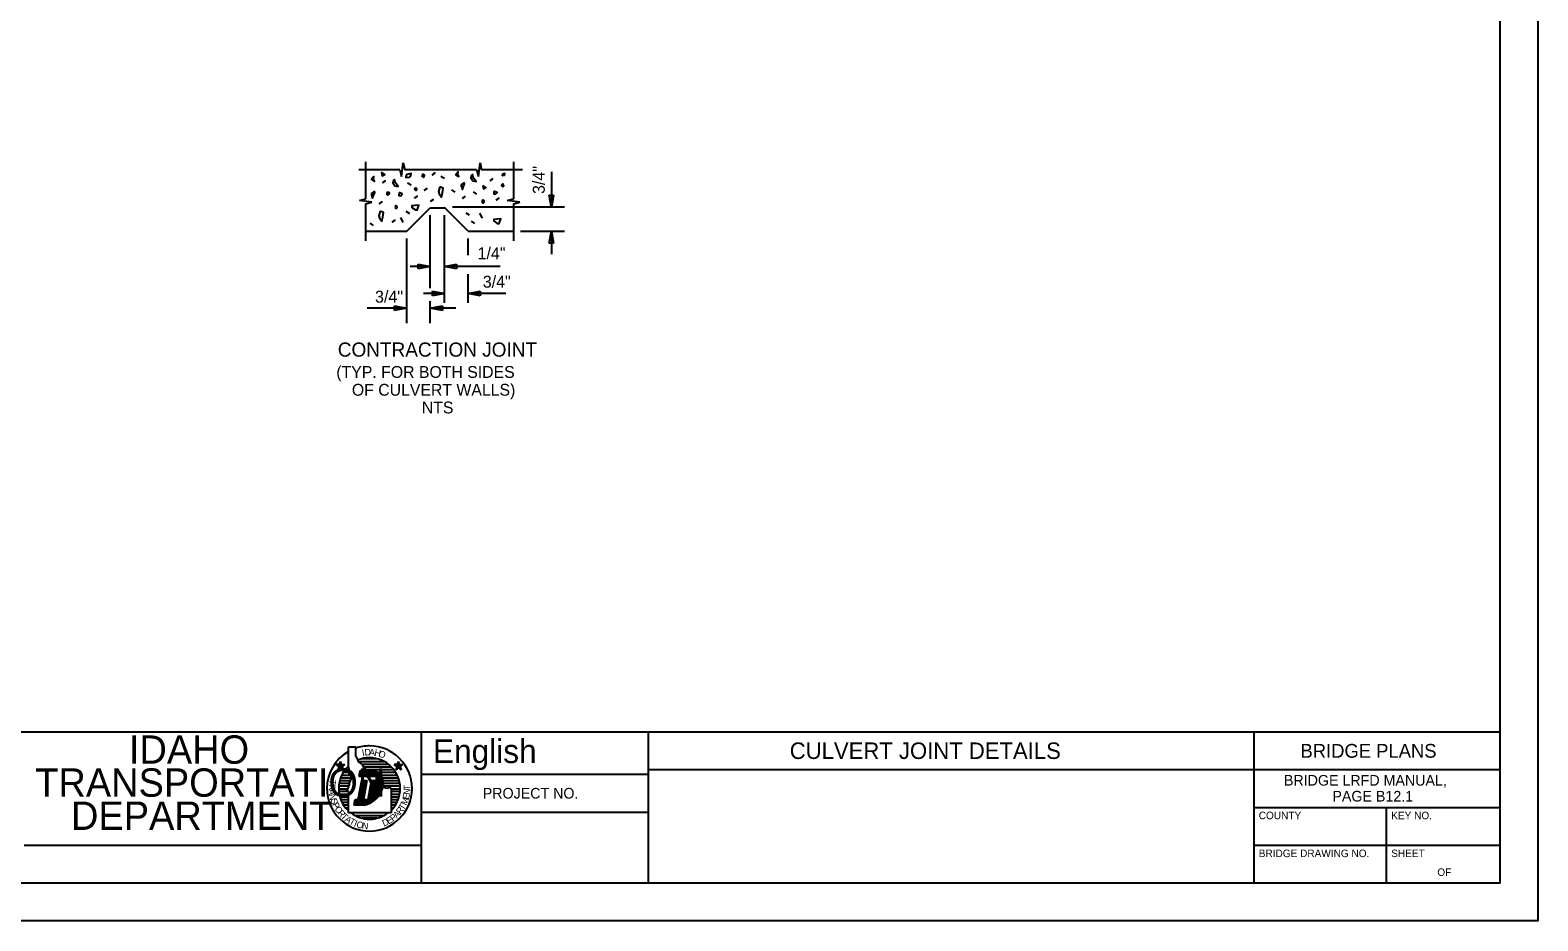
# Model space of a CAD drawing. Extents: x 0 to 22.7, y 0 to 15.7.
# Drawn here: x 9.39 to 22.67, y 0 to 7.85 of the extents above; entities that cross this region are included whole.
import ezdxf

# ---------------------------------------------------------------- set-up
doc = ezdxf.new("R2010")
doc.units = 0
for name, color, linetype in [('BORDER_ANNO_Cutsheet', 7, 'Continuous'), ('BRDG_ANNO_Anno-Sheet', 7, 'Continuous'), ('BRDG_ANNO_General-Notes', 7, 'Continuous'), ('BRDG_BASE_Obj-Line', 7, 'Continuous'), ('BRDG_BASE_Pattern', 7, 'Continuous')]:
    doc.layers.add(name, color=color, linetype=linetype)

msp = doc.modelspace()

# ---------------------------------------------------------------- linework, layer by layer
at = {"layer": 'BORDER_ANNO_Cutsheet'}
msp.add_lwpolyline([(0, 14.667), (22.667, 14.667), (22.667, 0), (0, 0)], close=True, dxfattribs=at)
at = {"layer": 'BRDG_ANNO_Anno-Sheet'}
for p, q in [((1, 1.667), (12.833, 1.667)), ((12.833, 0.333), (12.833, 1.667)), ((12.833, 1.667), (22.333, 1.667)), ((14.833, 0.333), (14.833, 1.667)), ((20.167, 0.333), (20.167, 1.667)), ((12.19, 1.362), (12.19, 1.535)), ((12.19, 1.535), (12.255, 1.535)), ((12.255, 1.449), (12.255, 1.535)), ((12.134, 1.36), (12.082, 1.377)), ((12.11, 1.377), (12.082, 1.377)), ((12.105, 1.36), (12.082, 1.377)), ((12.129, 1.377), (12.096, 1.332)), ((12.105, 1.36), (12.096, 1.332)), ((12.12, 1.349), (12.096, 1.332)), ((12.105, 1.36), (12.158, 1.377)), ((12.11, 1.377), (12.12, 1.405)), ((12.11, 1.377), (12.143, 1.332)), ((12.12, 1.349), (12.12, 1.405)), ((12.129, 1.377), (12.12, 1.405)), ((12.12, 1.349), (12.143, 1.332)), ((12.129, 1.377), (12.158, 1.377)), ((12.134, 1.36), (12.158, 1.377)), ((12.134, 1.36), (12.143, 1.332)), ((12.161, 1.334), (12.196, 1.334)), ((12.183, 1.357), (12.191, 1.357)), ((12.196, 1.337), (12.19, 1.362)), ((12.196, 1.317), (12.196, 1.337)), ((12.255, 1.449), (12.273, 1.417)), ((12.273, 1.417), (12.276, 1.403)), ((12.276, 1.403), (12.311, 1.379)), ((12.278, 1.405), (12.5, 1.405)), ((12.31, 1.43), (12.439, 1.43)), ((12.31, 1.382), (12.538, 1.382)), ((12.311, 1.379), (12.322, 1.351)), ((12.319, 1.357), (12.567, 1.357)), ((12.322, 1.351), (12.356, 1.324)), ((12.344, 1.334), (12.588, 1.334)), ((12.645, 1.36), (12.592, 1.377)), ((12.616, 1.36), (12.592, 1.377)), ((12.621, 1.377), (12.592, 1.377)), ((12.64, 1.377), (12.607, 1.332)), ((12.616, 1.36), (12.607, 1.332)), ((12.63, 1.349), (12.607, 1.332)), ((12.616, 1.36), (12.668, 1.377)), ((12.621, 1.377), (12.63, 1.405)), ((12.621, 1.377), (12.654, 1.332)), ((12.63, 1.349), (12.63, 1.405)), ((12.64, 1.377), (12.63, 1.405)), ((12.63, 1.349), (12.654, 1.332)), ((12.64, 1.377), (12.668, 1.377)), ((12.645, 1.36), (12.668, 1.377)), ((12.645, 1.36), (12.654, 1.332)), ((14.833, 1.333), (20.167, 1.333)), ((20.167, 1.333), (22.333, 1.333)), ((12.108, 1.214), (12.199, 1.214)), ((12.114, 1.238), (12.207, 1.238)), ((12.121, 1.262), (12.213, 1.262)), ((12.131, 1.285), (12.199, 1.285)), ((12.145, 1.31), (12.195, 1.31)), ((12.19, 1.181), (12.2, 1.202)), ((12.196, 1.299), (12.196, 1.317)), ((12.2, 1.285), (12.196, 1.299)), ((12.214, 1.278), (12.2, 1.285)), ((12.2, 1.219), (12.207, 1.233)), ((12.2, 1.202), (12.2, 1.219)), ((12.207, 1.233), (12.214, 1.25)), ((12.214, 1.261), (12.214, 1.278)), ((12.214, 1.25), (12.214, 1.261)), ((12.276, 1.07), (12.307, 1.237)), ((12.277, 1.021), (12.318, 1.237)), ((12.283, 1.271), (12.294, 1.324)), ((12.441, 1.271), (12.283, 1.271)), ((12.288, 1.021), (12.329, 1.237)), ((12.293, 1.271), (12.303, 1.324)), ((12.294, 1.324), (12.408, 1.324)), ((12.299, 1.021), (12.339, 1.237)), ((12.303, 1.271), (12.313, 1.324)), ((12.307, 1.237), (12.353, 1.237)), ((12.31, 1.021), (12.35, 1.237)), ((12.314, 1.271), (12.324, 1.324)), ((12.353, 1.237), (12.322, 1.07)), ((12.325, 1.271), (12.335, 1.324)), ((12.335, 1.271), (12.345, 1.324)), ((12.346, 1.271), (12.355, 1.324)), ((12.356, 1.271), (12.366, 1.324)), ((12.362, 1.07), (12.394, 1.237)), ((12.365, 1.032), (12.403, 1.237)), ((12.367, 1.271), (12.377, 1.324)), ((12.376, 1.037), (12.413, 1.237)), ((12.377, 1.271), (12.387, 1.324)), ((12.387, 1.042), (12.424, 1.237)), ((12.388, 1.271), (12.398, 1.324)), ((12.394, 1.237), (12.435, 1.237)), ((12.399, 1.271), (12.409, 1.324)), ((12.4, 1.05), (12.448, 1.308)), ((12.409, 1.271), (12.419, 1.321)), ((12.412, 1.057), (12.457, 1.301)), ((12.42, 1.271), (12.429, 1.318)), ((12.424, 1.067), (12.466, 1.292)), ((12.43, 1.271), (12.438, 1.313)), ((12.435, 1.237), (12.441, 1.271)), ((12.437, 1.079), (12.475, 1.283)), ((12.446, 1.31), (12.605, 1.31)), ((12.45, 1.093), (12.483, 1.271)), ((12.465, 1.113), (12.491, 1.255)), ((12.473, 1.285), (12.618, 1.285)), ((12.481, 1.145), (12.497, 1.23)), ((12.488, 1.262), (12.629, 1.262)), ((12.496, 1.238), (12.636, 1.238)), ((12.498, 1.214), (12.642, 1.214)), ((12.833, 1.292), (14.833, 1.292)), ((12.104, 1.165), (12.185, 1.165)), ((12.105, 1.19), (12.194, 1.19)), ((12.105, 1.142), (12.188, 1.142)), ((12.109, 1.117), (12.199, 1.117)), ((12.114, 1.094), (12.189, 1.094)), ((12.122, 1.07), (12.188, 1.07)), ((12.179, 1.15), (12.186, 1.167)), ((12.19, 1.14), (12.179, 1.15)), ((12.186, 1.167), (12.19, 1.181)), ((12.196, 1.129), (12.19, 1.14)), ((12.19, 1.101), (12.2, 1.112)), ((12.19, 0.952), (12.19, 1.101)), ((12.2, 1.122), (12.196, 1.129)), ((12.2, 1.112), (12.2, 1.122)), ((12.24, 1.021), (12.249, 1.07)), ((12.246, 1.021), (12.255, 1.07)), ((12.249, 1.07), (12.276, 1.07)), ((12.257, 1.021), (12.266, 1.07)), ((12.267, 1.021), (12.276, 1.07)), ((12.32, 1.021), (12.329, 1.07)), ((12.322, 1.07), (12.362, 1.07)), ((12.331, 1.022), (12.34, 1.07)), ((12.342, 1.025), (12.35, 1.07)), ((12.353, 1.028), (12.361, 1.07)), ((12.494, 1.185), (12.499, 1.177)), ((12.495, 1.19), (12.645, 1.19)), ((12.499, 1.177), (12.52, 1.174)), ((12.52, 1.174), (12.54, 1.171)), ((12.54, 1.171), (12.551, 1.185)), ((12.551, 1.185), (12.565, 1.164)), ((12.563, 1.165), (12.646, 1.165)), ((12.565, 1.164), (12.565, 0.952)), ((12.565, 1.142), (12.645, 1.142)), ((12.565, 1.117), (12.641, 1.117)), ((12.565, 1.094), (12.636, 1.094)), ((12.565, 1.07), (12.627, 1.07)), ((12.133, 1.045), (12.188, 1.045)), ((12.147, 1.022), (12.189, 1.022)), ((12.164, 0.997), (12.188, 0.997)), ((12.185, 0.974), (12.189, 0.974)), ((12.565, 0.952), (12.19, 0.952)), ((12.328, 1.021), (12.24, 1.021)), ((12.565, 1.045), (12.617, 1.045)), ((12.565, 1.022), (12.603, 1.022)), ((12.565, 0.997), (12.587, 0.997)), ((12.833, 0.958), (14.833, 0.958)), ((20.167, 1), (22.333, 1)), ((21.333, 0.333), (21.333, 1)), ((12.5, 0.927), (12.248, 0.927)), ((12.439, 0.904), (12.312, 0.904)), ((9.333, 0.667), (12.833, 0.667)), ((20.167, 0.667), (22.333, 0.667))]:
    msp.add_line(p, q, dxfattribs=at)
msp.add_lwpolyline([(1, 14.333), (22.333, 14.333), (22.333, 0.333), (1, 0.333)], close=True, dxfattribs=at)
for centre, radius, start, end in [((12.375, 1.167), 0.375, 119.6331, 180), ((12.375, 1.167), 0.375, 90, 108.596), ((12.375, 1.167), 0.375, 0, 90), ((12.375, 1.167), 0.271, 133.1926, 180), ((12.375, 1.167), 0.271, 90, 112.1452), ((12.375, 1.167), 0.271, 0, 90), ((12.389, 1.216), 0.109, 343.4981, 79.7362), ((12.375, 1.167), 0.375, 180, 270), ((12.375, 1.167), 0.271, 180.2644, 226.7946), ((12.29, 1.225), 0.208, 280.6479, 348.7719), ((12.375, 1.167), 0.375, 270, 0), ((12.375, 1.167), 0.271, 314.427, 0), ((12.375, 1.167), 0.271, 232.5658, 270), ((12.375, 1.167), 0.271, 270, 307.4536)]:
    msp.add_arc(centre, radius, start, end, dxfattribs=at)
at = {"layer": 'BRDG_ANNO_General-Notes'}
for p, q in [((13.977, 6.601), (13.977, 6.289)), ((13.957, 6.396), (13.997, 6.396)), ((13.977, 6.289), (13.957, 6.396)), ((13.997, 6.396), (13.977, 6.289)), ((14.092, 6.29), (13.105, 6.29)), ((12.91, 5.576), (12.91, 6.219)), ((13.035, 5.447), (13.035, 6.219)), ((12.703, 5.268), (12.703, 6.015)), ((13.244, 5.869), (13.244, 6.015)), ((13.704, 6.08), (14.092, 6.08)), ((13.957, 5.973), (13.977, 6.08)), ((13.977, 6.08), (13.977, 5.875)), ((13.977, 6.08), (13.997, 5.973)), ((13.997, 5.973), (13.957, 5.973)), ((12.91, 5.768), (12.733, 5.768)), ((12.804, 5.748), (12.804, 5.788)), ((12.804, 5.788), (12.91, 5.768)), ((12.91, 5.768), (12.804, 5.748)), ((13.035, 5.768), (13.142, 5.788)), ((13.527, 5.768), (13.035, 5.768)), ((13.142, 5.748), (13.035, 5.768)), ((13.142, 5.788), (13.142, 5.748)), ((13.244, 5.447), (13.244, 5.7)), ((13.035, 5.53), (12.85, 5.53)), ((12.91, 5.268), (12.91, 5.461)), ((12.929, 5.51), (12.929, 5.55)), ((12.929, 5.55), (13.035, 5.53)), ((13.035, 5.53), (12.929, 5.51)), ((13.244, 5.53), (13.35, 5.55)), ((13.575, 5.53), (13.244, 5.53)), ((13.35, 5.51), (13.244, 5.53)), ((13.35, 5.55), (13.35, 5.51)), ((12.702, 5.401), (12.354, 5.401)), ((12.596, 5.381), (12.596, 5.421)), ((12.596, 5.421), (12.702, 5.401)), ((12.702, 5.401), (12.596, 5.381)), ((12.91, 5.401), (13.017, 5.421)), ((13.136, 5.401), (12.91, 5.401)), ((13.017, 5.381), (12.91, 5.401)), ((13.017, 5.421), (13.017, 5.381))]:
    msp.add_line(p, q, dxfattribs=at)
at = {"layer": 'BRDG_BASE_Obj-Line'}
for p, q in [((12.341, 6.689), (12.341, 6.363)), ((12.656, 6.562), (12.671, 6.68)), ((12.671, 6.68), (12.686, 6.621)), ((13.334, 6.562), (13.349, 6.68)), ((13.349, 6.68), (13.363, 6.621)), ((13.643, 6.689), (13.643, 6.363)), ((12.641, 6.621), (12.28, 6.621)), ((12.641, 6.621), (12.656, 6.562)), ((13.319, 6.621), (12.686, 6.621)), ((13.319, 6.621), (13.334, 6.562)), ((13.724, 6.621), (13.363, 6.621)), ((12.286, 6.349), (12.341, 6.363)), ((12.397, 6.335), (12.286, 6.349)), ((12.341, 6.321), (12.397, 6.335)), ((12.341, 6.321), (12.341, 5.995)), ((12.703, 6.078), (12.91, 6.286)), ((12.91, 6.286), (13.035, 6.286)), ((13.244, 6.078), (13.035, 6.287)), ((13.587, 6.349), (13.643, 6.363)), ((13.698, 6.335), (13.587, 6.349)), ((13.643, 6.321), (13.698, 6.335)), ((13.643, 6.321), (13.643, 5.995)), ((12.339, 6.078), (12.703, 6.078)), ((13.244, 6.078), (13.64, 6.078))]:
    msp.add_line(p, q, dxfattribs=at)
at = {"layer": 'BRDG_BASE_Pattern'}
for p, q in [((13.005, 6.565), (13.036, 6.546)), ((12.71, 6.506), (12.741, 6.487)), ((13.097, 6.442), (13.127, 6.423)), ((13.288, 6.425), (13.318, 6.406)), ((12.696, 6.255), (12.727, 6.236)), ((13.223, 6.242), (13.254, 6.223)), ((12.378, 6.149), (12.408, 6.13)), ((12.647, 6.2), (12.67, 6.155)), ((13.27, 6.168), (13.301, 6.148)), ((13.344, 6.238), (13.367, 6.193))]:
    msp.add_line(p, q, dxfattribs=at)
for points in [[(12.409, 6.558), (12.393, 6.534), (12.42, 6.518), (12.41, 6.54), (12.414, 6.56)], [(12.481, 6.598), (12.486, 6.566), (12.509, 6.58)], [(12.491, 6.506), (12.514, 6.524)], [(12.587, 6.53), (12.581, 6.504), (12.599, 6.479), (12.627, 6.473), (12.604, 6.504), (12.595, 6.535)], [(12.701, 6.579), (12.696, 6.552), (12.728, 6.556), (12.737, 6.561), (12.742, 6.588)], [(12.839, 6.577), (12.839, 6.56), (12.847, 6.554), (12.85, 6.556), (12.857, 6.563), (12.861, 6.572), (12.858, 6.577), (12.853, 6.579), (12.851, 6.579), (12.846, 6.578)], [(12.927, 6.573), (12.95, 6.592)], [(13.152, 6.6), (13.136, 6.576), (13.163, 6.56), (13.153, 6.582), (13.157, 6.602)], [(13.274, 6.574), (13.269, 6.548), (13.286, 6.523), (13.315, 6.517), (13.292, 6.547), (13.282, 6.579)], [(13.437, 6.523), (13.459, 6.541)], [(13.547, 6.583), (13.545, 6.569), (13.561, 6.572), (13.565, 6.574), (13.568, 6.588)], [(12.389, 6.411), (12.403, 6.369), (12.403, 6.374), (12.422, 6.42), (12.417, 6.429)], [(12.529, 6.419), (12.529, 6.401), (12.537, 6.396), (12.54, 6.398), (12.546, 6.405), (12.551, 6.414), (12.548, 6.419), (12.543, 6.421), (12.541, 6.421), (12.536, 6.42)], [(12.636, 6.419), (12.635, 6.394), (12.65, 6.391), (12.664, 6.407)], [(12.772, 6.369), (12.795, 6.387)], [(12.779, 6.461), (12.773, 6.448), (12.78, 6.441), (12.788, 6.441), (12.792, 6.445), (12.792, 6.452), (12.79, 6.455), (12.787, 6.459)], [(12.858, 6.438), (12.881, 6.456)], [(12.995, 6.47), (12.982, 6.428), (12.989, 6.408), (13.009, 6.38), (13.018, 6.417), (13.025, 6.458)], [(13.179, 6.488), (13.193, 6.446), (13.193, 6.451), (13.211, 6.497), (13.206, 6.506)], [(13.193, 6.367), (13.216, 6.385)], [(13.374, 6.483), (13.378, 6.451), (13.401, 6.465)], [(13.471, 6.432), (13.47, 6.407), (13.485, 6.404), (13.499, 6.42)], [(13.545, 6.494), (13.539, 6.481), (13.546, 6.474), (13.554, 6.474), (13.558, 6.478), (13.558, 6.485), (13.557, 6.488), (13.553, 6.492)], [(12.47, 6.255), (12.456, 6.214), (12.463, 6.193), (12.483, 6.166), (12.492, 6.202), (12.499, 6.244)], [(12.461, 6.319), (12.484, 6.337)], [(12.6, 6.292), (12.604, 6.281), (12.607, 6.281), (12.611, 6.282), (12.615, 6.285), (12.618, 6.292), (12.617, 6.299), (12.611, 6.3), (12.609, 6.303), (12.605, 6.303)], [(12.777, 6.304), (12.749, 6.302), (12.749, 6.288), (12.779, 6.267), (12.795, 6.265), (12.811, 6.309)], [(12.912, 6.34), (12.935, 6.359)], [(13.366, 6.34), (13.37, 6.329), (13.373, 6.329), (13.378, 6.33), (13.381, 6.333), (13.385, 6.34), (13.384, 6.347), (13.378, 6.348), (13.375, 6.351), (13.371, 6.351)], [(13.491, 6.353), (13.514, 6.371)], [(12.575, 6.157), (12.598, 6.175)], [(13.498, 6.185), (13.471, 6.182), (13.471, 6.169), (13.5, 6.148), (13.516, 6.146), (13.532, 6.189)]]:
    msp.add_lwpolyline(points, close=True, dxfattribs=at)

# ---------------------------------------------------------------- texts
at = {"layer": 'BRDG_ANNO_Anno-Sheet'}
for s, height, p in [('IDAHO', 0.25, (10.256, 1.385)), ('English', 0.2083, (12.934, 1.391)), ('CULVERT JOINT DETAILS', 0.14542, (16.077, 1.427)), ('BRIDGE PLANS', 0.12125, (20.576, 1.438)), ('TRANSPORTATION', 0.25, (9.431, 1.094)), ('BRIDGE LRFD MANUAL,', 0.09375, (20.43, 1.192)), ('PROJECT NO.', 0.09375, (13.373, 1.078)), ('PAGE B12.1', 0.0938, (20.857, 1.052)), ('DEPARTMENT', 0.25, (9.746, 0.802)), ('COUNTY', 0.0663, (20.208, 0.896)), ('KEY NO.', 0.0663, (21.375, 0.896)), ('BRIDGE DRAWING NO.', 0.06625, (20.208, 0.562)), ('SHEET', 0.0663, (21.375, 0.562)), ('OF', 0.0663, (21.781, 0.396))]:
    msp.add_text(s, height=height, dxfattribs=at).set_placement(p)
for s, rotation, p in [('I', 11.9519, (12.315, 1.452)), ('D', 5.2118, (12.334, 1.456)), ('A', 357.8718, (12.371, 1.459)), ('H', 349.6318, (12.415, 1.456)), ('O', 342.1917, (12.45, 1.449)), ('R', 266.0275, (12.018, 1.205)), ('T', 259.4265, (12.025, 1.25)), ('T', 90.4926, (12.735, 1.153)), ('A', 273.764, (12.015, 1.16)), ('N', 280.3758, (12.019, 1.114)), ('S', 287.9279, (12.029, 1.069)), ('M', 67.7139, (12.7, 1.014)), ('E', 75.6105, (12.72, 1.065)), ('N', 83.1932, (12.73, 1.109)), ('P', 295.4976, (12.044, 1.027)), ('O', 302.6446, (12.064, 0.987)), ('R', 309.9079, (12.089, 0.948)), ('T', 317.1211, (12.118, 0.914)), ('P', 37.6656, (12.582, 0.873)), ('A', 45, (12.617, 0.9)), ('R', 52.3344, (12.649, 0.934)), ('T', 59.0362, (12.676, 0.97)), ('A', 324.6375, (12.152, 0.884)), ('T', 331.7503, (12.19, 0.858)), ('I', 337.0213, (12.233, 0.836)), ('O', 343.3287, (12.255, 0.827)), ('N', 351.6598, (12.306, 0.813)), ('D', 22.9887, (12.502, 0.83)), ('E', 30.5476, (12.544, 0.849))]:
    msp.add_text(s, height=0.0579, rotation=rotation, dxfattribs=at).set_placement(p)
at = {"layer": 'BRDG_ANNO_General-Notes'}
for s, rotation, p in [('3/4"', 90.011, (13.919, 6.407)), ('1/4"', 0.011, (13.327, 5.831)), ('3/4"', 0.011, (13.373, 5.581))]:
    msp.add_text(s, height=0.1056, rotation=rotation, dxfattribs=at).set_placement(p)
for s, height, p in [('3/4"', 0.1056, (12.424, 5.449)), ('CONTRACTION JOINT', 0.125, (12.096, 4.973)), ('(TYP. FOR BOTH SIDES', 0.10417, (12.083, 4.786)), ('OF CULVERT WALLS)', 0.10417, (12.22, 4.629)), ('NTS', 0.1042, (12.836, 4.473))]:
    msp.add_text(s, height=height, dxfattribs=at).set_placement(p)

doc.saveas('drawing.dxf')
